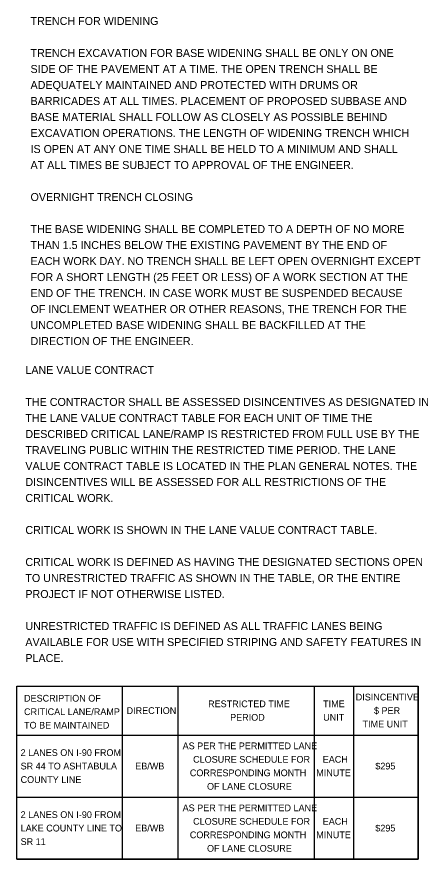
# Model space of a CAD drawing. Extents: x -26.4 to 34, y 0 to 22.
# Drawn here: x -26.41 to -19.23, y 1.87 to 16.61 of the extents above; entities that cross this region are included whole.
import ezdxf

# ---------------------------------------------------------------- set-up
doc = ezdxf.new("R2010")
doc.units = 0
doc.layers.add('SH_Text', color=7, linetype='Continuous')

msp = doc.modelspace()

# ---------------------------------------------------------------- linework, layer by layer
at = {"layer": 'SH_Text'}
for p, q in [((-24.569, 1.872), (-24.569, 4.9)), ((-23.596, 2.957), (-23.596, 4.9)), ((-23.596, 1.872), (-23.596, 4.9)), ((-21.21, 1.872), (-21.21, 4.9)), ((-20.524, 1.872), (-20.524, 4.9)), ((-19.404, 1.872), (-19.404, 4.9)), ((-26.414, 4.043), (-19.404, 4.043)), ((-26.414, 2.957), (-20.38, 2.957)), ((-26.414, 2.957), (-19.404, 2.957)), ((-26.414, 1.872), (-19.404, 1.872))]:
    msp.add_line(p, q, dxfattribs=at)
msp.add_lwpolyline([(-26.414, 4.9), (-19.404, 4.9), (-19.404, 1.872), (-26.414, 1.872)], close=True, dxfattribs=at)

# ---------------------------------------------------------------- texts
for s, height, p in [('TRENCH FOR WIDENING', 0.14, (-26.175, 16.465)), ('TRENCH EXCAVATION FOR BASE WIDENING SHALL BE ONLY ON ONE ', 0.14, (-26.175, 15.905)), ('SIDE OF THE PAVEMENT AT A TIME. THE OPEN TRENCH SHALL BE ', 0.14, (-26.175, 15.625)), ('ADEQUATELY MAINTAINED AND PROTECTED WITH DRUMS OR ', 0.14, (-26.175, 15.345)), ('BARRICADES AT ALL TIMES. PLACEMENT OF PROPOSED SUBBASE AND ', 0.14, (-26.175, 15.065)), ('BASE MATERIAL SHALL FOLLOW AS CLOSELY AS POSSIBLE BEHIND ', 0.14, (-26.175, 14.785)), ('EXCAVATION OPERATIONS. THE LENGTH OF WIDENING TRENCH WHICH ', 0.14, (-26.175, 14.505)), ('IS OPEN AT ANY ONE TIME SHALL BE HELD TO A MINIMUM AND SHALL ', 0.14, (-26.175, 14.225)), ('AT ALL TIMES BE SUBJECT TO APPROVAL OF THE ENGINEER.', 0.14, (-26.175, 13.945)), ('OVERNIGHT TRENCH CLOSING', 0.14, (-26.175, 13.385)), ('THE BASE WIDENING SHALL BE COMPLETED TO A DEPTH OF NO MORE ', 0.14, (-26.175, 12.825)), ('THAN 1.5 INCHES BELOW THE EXISTING PAVEMENT BY THE END OF ', 0.14, (-26.175, 12.545)), ('EACH WORK DAY. NO TRENCH SHALL BE LEFT OPEN OVERNIGHT EXCEPT ', 0.14, (-26.175, 12.265)), ('FOR A SHORT LENGTH (25 FEET OR LESS) OF A WORK SECTION AT THE ', 0.14, (-26.175, 11.985)), ('END OF THE TRENCH. IN CASE WORK MUST BE SUSPENDED BECAUSE ', 0.14, (-26.175, 11.705)), ('OF INCLEMENT WEATHER OR OTHER REASONS, THE TRENCH FOR THE ', 0.14, (-26.175, 11.425)), ('UNCOMPLETED BASE WIDENING SHALL BE BACKFILLED AT THE ', 0.14, (-26.175, 11.145)), ('DIRECTION OF THE ENGINEER.', 0.14, (-26.175, 10.865)), ('LANE VALUE CONTRACT', 0.14, (-26.265, 10.36)), ('THE CONTRACTOR SHALL BE ASSESSED DISINCENTIVES AS DESIGNATED IN ', 0.14, (-26.265, 9.8)), ('THE LANE VALUE CONTRACT TABLE FOR EACH UNIT OF TIME THE ', 0.14, (-26.265, 9.52)), ('DESCRIBED CRITICAL LANE/RAMP IS RESTRICTED FROM FULL USE BY THE ', 0.14, (-26.265, 9.24)), ('TRAVELING PUBLIC WITHIN THE RESTRICTED TIME PERIOD. THE LANE ', 0.14, (-26.265, 8.96)), ('VALUE CONTRACT TABLE IS LOCATED IN THE PLAN GENERAL NOTES. THE ', 0.14, (-26.265, 8.68)), ('DISINCENTIVES WILL BE ASSESSED FOR ALL RESTRICTIONS OF THE ', 0.14, (-26.265, 8.4)), ('CRITICAL WORK.', 0.14, (-26.265, 8.12)), ('CRITICAL WORK IS SHOWN IN THE LANE VALUE CONTRACT TABLE.', 0.14, (-26.265, 7.56)), ('CRITICAL WORK IS DEFINED AS HAVING THE DESIGNATED SECTIONS OPEN ', 0.14, (-26.265, 7)), ('TO UNRESTRICTED TRAFFIC AS SHOWN IN THE TABLE, OR THE ENTIRE ', 0.14, (-26.265, 6.72)), ('PROJECT IF NOT OTHERWISE LISTED.', 0.14, (-26.265, 6.44)), ('UNRESTRICTED TRAFFIC IS DEFINED AS ALL TRAFFIC LANES BEING ', 0.14, (-26.265, 5.88)), ('AVAILABLE FOR USE WITH SPECIFIED STRIPING AND SAFETY FEATURES IN ', 0.14, (-26.265, 5.6)), ('PLACE.', 0.14, (-26.265, 5.32)), ('DESCRIPTION OF ', 0.11801, (-26.288, 4.628)), ('DISINCENTIVE', 0.11801, (-20.492, 4.648)), ('RESTRICTED TIME', 0.11801, (-23.072, 4.53)), ('TIME', 0.118, (-21.062, 4.53)), ('CRITICAL LANE/RAMP', 0.11801, (-26.288, 4.392)), ('DIRECTION', 0.118, (-24.496, 4.412)), ('$ PER', 0.118, (-20.173, 4.412)), ('TO BE MAINTAINED', 0.11801, (-26.288, 4.156)), ('PERIOD', 0.118, (-22.687, 4.294)), ('UNIT', 0.118, (-21.061, 4.294)), ('TIME UNIT', 0.118, (-20.373, 4.176)), ('AS PER THE PERMITTED LANE', 0.11801, (-23.517, 3.795)), ('2 LANES ON I-90 FROM', 0.11801, (-26.348, 3.677)), ('SR 44 TO ASHTABULA', 0.11801, (-26.348, 3.441)), ('EB/WB', 0.118, (-24.345, 3.441)), ('CLOSURE SCHEDULE FOR', 0.11801, (-23.334, 3.559)), ('EACH', 0.118, (-21.069, 3.559)), ('$295', 0.118, (-20.15, 3.441)), ('CORRESPONDING MONTH', 0.11801, (-23.391, 3.323)), ('MINUTE', 0.118, (-21.182, 3.323)), ('COUNTY LINE', 0.11801, (-26.348, 3.205)), ('OF LANE CLOSURE', 0.11801, (-23.091, 3.087)), ('AS PER THE PERMITTED LANE', 0.11801, (-23.517, 2.71)), ('2 LANES ON I-90 FROM', 0.11801, (-26.348, 2.592)), ('CLOSURE SCHEDULE FOR', 0.11801, (-23.334, 2.474)), ('EACH', 0.118, (-21.069, 2.474)), ('LAKE COUNTY LINE TO', 0.11801, (-26.348, 2.356)), ('EB/WB', 0.118, (-24.345, 2.356)), ('$295', 0.118, (-20.15, 2.356)), ('SR 11', 0.118, (-26.348, 2.12)), ('CORRESPONDING MONTH', 0.11801, (-23.391, 2.238)), ('MINUTE', 0.118, (-21.182, 2.238)), ('OF LANE CLOSURE', 0.11801, (-23.091, 2.002))]:
    msp.add_text(s, height=height, dxfattribs=at).set_placement(p)

doc.saveas('drawing.dxf')
